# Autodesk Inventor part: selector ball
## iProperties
Created: 2006-04
Part Number: selector ball
Document SubType Name: Modeling
Designer: Калинин
Author: Калинин
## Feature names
1. Вращение1 [Revolution]
